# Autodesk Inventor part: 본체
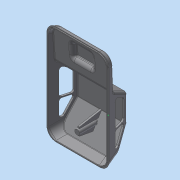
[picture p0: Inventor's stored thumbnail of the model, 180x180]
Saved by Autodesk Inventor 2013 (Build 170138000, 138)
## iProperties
Created: 2015-05
Part Number: 본체
Material: 일반
Document SubType Name: Modeling
Designer: Administrator
Density: 1 g/cm^3
Author: Administrator
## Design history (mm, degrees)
sketch "스케치2"
  geometry: L1 (-38, 31)-(38, 31); L2 (38, 31)-(38, 0); L3 (38, 0)-(-38, 0); L4 (-38, 0)-(-38, 31); 2 further points
  constraints: 8 end point, 2 parallel, 1 coincident, 1 horizontal, 1 midpoint, 1 perpendicular
  dimensions: "d9" = 76 distance of L2.end L3.end; "d11" = 31 distance of L1.end L2.end
extrude "돌출1" new body sketch "스케치2" stored distance "d12" = 122; taper "d13" = 0 deg
sketch "스케치3"
  geometry: L1 (38, 31)-(-38, 31) reference; L2 (-38, 31)-(-38, 0) reference; L3 (-38, 0)-(38, 0) reference; L4 (38, 0)-(38, 31) reference; L5 (-38, 0)-(-37, 0); L6 (-37, 0)-(-37, 1); L7 (-37, 1)-(-38, 1); L8 (-38, 1)-(-38, 0); L9 (38, 0)-(37, 0); L10 (37, 0)-(37, 1); L11 (37, 1)-(38, 1); L12 (38, 1)-(38, 0); L13 (-38, 1)-(-29.962, 31); L14 (38, 1)-(29.962, 31); 1 further point
  constraints: 20 end point, 4 parallel, 2 horizontal, 2 perpendicular, 2 point on line
  dimensions: "d14" = 1 distance of L10.end L11.end; "d16" = 1 distance of L9.end L10.end; "d17" = 1 distance of L6.end L7.end; "d18" = 1 distance of L5.end L6.end; "d19" = 105 deg angle of L3 L14; "d20" = 105 deg angle of L3 L13
node "작업 평면1"
extrude "돌출3" cut sketch "스케치3" distance "d24" = 122; taper "d25" = 0 deg
sketch "스케치5"
  geometry: L1 (1, 61)-(31, 61) reference; L2 (31, 61)-(31, -61) reference; L3 (31, -61)-(1, -61) reference; L4 (0, 61)-(0, -61) reference; L5 (1, 61)-(7, 59.392); L6 (7, 59.392)-(9.117, 19); L7 (9.117, 19)-(31, 5.326); L8 (31, -27.805)-(11, -61); L9 (12.925, -57.805)-(1, -61); L10 (0, 61)-(1, 61); L11 (1, 61)-(1, 60); L12 (1, 60)-(0, 60); L13 (0, 60)-(0, 61); L14 (0, -61)-(1, -61); L15 (1, -61)-(1, -60); L16 (1, -60)-(0, -60); L17 (0, -60)-(0, -61); L18 (1, -61)-(1, 61) reference; 1 further point
  constraints: 26 end point, 4 parallel, 4 point on line, 2 horizontal, 2 perpendicular
  dimensions: "d26" = 1 distance of L14.end L15.end; "d28" = 1 distance of L10.end L11.end; "d29" = 6 horizontal distance of L5.end L1.start; "d30" = 42 vertical distance of L6.end L1.start; "d31" = 105 deg angle of L4 L5; "d32" = 3 deg angle of L18 L6; "d33" = 125 deg angle of L7 L6; "d35" = 20 distance of L2.end L8.end; "d36" = 30 vertical distance of L9.start L8.start; "d37" = 105 deg angle of L4 L9
extrude "돌출4" cut sketch "스케치5" stored distance "d38" = 122; taper "d39" = 0 deg
sketch "스케치6"
  geometry: L1 (7, 59.392)-(9.117, 19) reference; L2 (1, 61)-(7, 59.392) reference; L3 (7.475, 50.324)-(8.522, 30.352); L4 (1, 61)-(20.944, 62.045); L5 (0, 61)-(0, -61) reference; L6 (7.475, 50.324)-(12.564, 48.769); L7 (8.522, 30.352)-(13.42, 32.431); L8 (12.564, 48.769)-(13.42, 32.431); 1 further point
  constraints: 10 end point, 2 point on line, 1 parallel
  dimensions: "d40" = 20 distance of L3.start L3.end; "d41" = 87 deg angle of L5 L4; "d43" = 11 distance from line of L3.start L4; "d44" = 70 deg angle of L1 L6; "d45" = 70 deg angle of L1 L7; "d46" = 5 distance between parallel lines of L1 L8
extrude "돌출5" join sketch "스케치6" stored distance "d47" = 26; taper "d48" = 0 deg
extrude "돌출6" cut sketch "스케치3" stored distance "d49" = 26; taper "d50" = 0 deg
extrude "돌출7" join sketch "스케치5" stored distance "d51" = 26; taper "d52" = 0 deg
extrude "돌출8" cut sketch "스케치5" stored distance "d53" = 26; taper "d54" = 0 deg
fillet "모깎기1" dims "d55" = 12
fillet "모깎기2" dims "d56" = 12
fillet "모깎기3" dims "d57" = 12
fillet "모깎기4" dims "d58" = 12
fillet "모깎기5" dims "d59" = 3
fillet "모깎기6" dims "d60" = 3
fillet "모깎기7" dims "d61" = 3
feature "쉘1" dims "d62" = 1, "d63" = 2
sketch "스케치8"
  geometry: 1 further point
sketch "스케치9"
  geometry: L1 (29.59, 6.207)-(10.441, 18.172) reference; L2 (31, -26.971)-(31, 3.663) reference; L3 (19.796, -46.401)-(30.57, -28.519) reference; L4 (15.59, 9.059)-(24.59, 3.436); L5 (26, 0.891)-(26, -19.073); L6 (11, -19.073)-(11, 6.515); L7 (0, -48)-(0, 48) reference; L8 (23, -22.073)-(14, -22.073); L9 (26, -26.415)-(16.57, -42.067); L10 (11, -40.519)-(11, -26.311); L11 (14, -23.311)-(23, -23.311); L12 (26, -26.415)-(26, -26.311); A1 r 3 centre (28, 3.663) between (31, 3.663) and (29.59, 6.207) reference; A2 r 3 centre (28, -26.971) between (30.57, -28.519) and (31, -26.971) reference; A3 r 3 centre (14, 6.515) between (15.59, 9.059) and (11, 6.515); A4 r 3 centre (23, 0.891) between (26, 0.891) and (24.59, 3.436); A5 r 3 centre (23, -19.073) between (23, -22.073) and (26, -19.073); A6 r 3 centre (14, -19.073) between (11, -19.073) and (14, -22.073); A7 r 3 centre (14, -26.311) between (14, -23.311) and (11, -26.311); A8 r 3 centre (23, -26.311) between (26, -26.311) and (23, -23.311); A9 r 3 centre (14, -40.519) between (11, -40.519) and (16.57, -42.067); 5 further points
  constraints: 16 end point, 14 point on circle, 14 tangent, 8 point on line, 7 centre point, 4 equal radius, 4 parallel, 4 perpendicular
  dimensions: "d65" = 5 distance between parallel lines of L1 L4; "d66" = 5 distance between parallel lines of L2 L5; "d67" = 15 distance between parallel lines of L5 L6; "d68" = 34 distance of point (11, -22.073) point (11, 11.927); "d69" = 5 distance between parallel lines of L9 L3; "d70" = 5 distance from line of L2 L9.start; "d71" = 15 horizontal distance of point (11, -51.311) L9.start; "d72" = 28 distance of point (11, -51.311) point (11, -23.311); "d73" = 3 radius of A3; "d74" = 3 radius of A7; "d75" = 3 radius of A9
extrude "돌출9" cut sketch "스케치9" stored distance "d76" = 26; taper "d77" = 0 deg
fillet "모깎기8" dims "d78" = 3
fillet "모깎기9" dims "d79" = 3
sketch "스케치10"
  geometry: L1 (29, 3.663)-(29, -26.971) reference; L2 (28.857, -27.487)-(18.083, -45.369) reference; L3 (18.083, -45.369)-(11.837, -55.736) reference; L4 (29, -26.971)-(2, -31.732); L5 (2, -31.732)-(2, -33.732); L6 (25.094, -33.732)-(0, -33.732); L7 (0, -33.732)-(0, -39.732); L8 (0, -39.732)-(21.479, -39.732); L9 (2, -39.732)-(2, -41.732); L10 (2, -41.732)-(18.519, -44.644); L11 (0, -48)-(0, 48) reference; L12 (0, -36.732)-(23.287, -36.732); L13 (21.479, -39.732)-(18.519, -44.644); A1 r 1 centre (28, -26.971) between (28.857, -27.487) and (29, -26.971) reference; 1 further point
  constraints: 18 end point, 7 point on line, 3 parallel, 3 perpendicular, 1 collinear, 1 midpoint
  dimensions: "d80" = 10 distance of L9.end L4.end; "d82" = 2 distance from line of L4.end L6; "d83" = 2 distance from line of L8 L9.end; "d85" = 80 deg angle of L11 L4; "d88" = 80 deg angle of L11 L10; "d89" = 2 distance of L6.end L5.end; "d90" = 2 distance of L7.end L9.start
revolve "회전1" stored, may be unused: angle "d91" = 90 deg
extrude "돌출10" join sketch "스케치10" stored distance "d92" = 2; taper "d93" = 0 deg
extrude "돌출11" join sketch "스케치10" stored distance "d94" = 2; taper "d95" = -4 deg
sketch "스케치11"
  geometry: C1 r 3 at (0, 0) reference; C2 r 3 at (0, 0); 1 further point
  constraints: 1 centre point, 1 coincident, 1 concentric
extrude "돌출12" join sketch "스케치11" stored distance "d96" = 2; taper "d97" = -4 deg
sketch "스케치13"
  geometry: L1 (55.319, -30.634)-(0, -30.634) reference; L2 (1.251, 34.029)-(54.068, 34.029) reference; 3 further points
  constraints: 1 midpoint, 1 vertical alignment, 1 other
  dimensions: "d98" = 50 distance from line of L2 point (27.66, -15.971)
feature "엠보싱1" sketch "스케치13" dims "d9" = 76, "d11" = 31, "d17" = 1, "d18" = 1, "d20" = 105 deg, "d99" = 0.5, "d100" = 0
node "솔리드1"
other parameters: "d23" = 38
